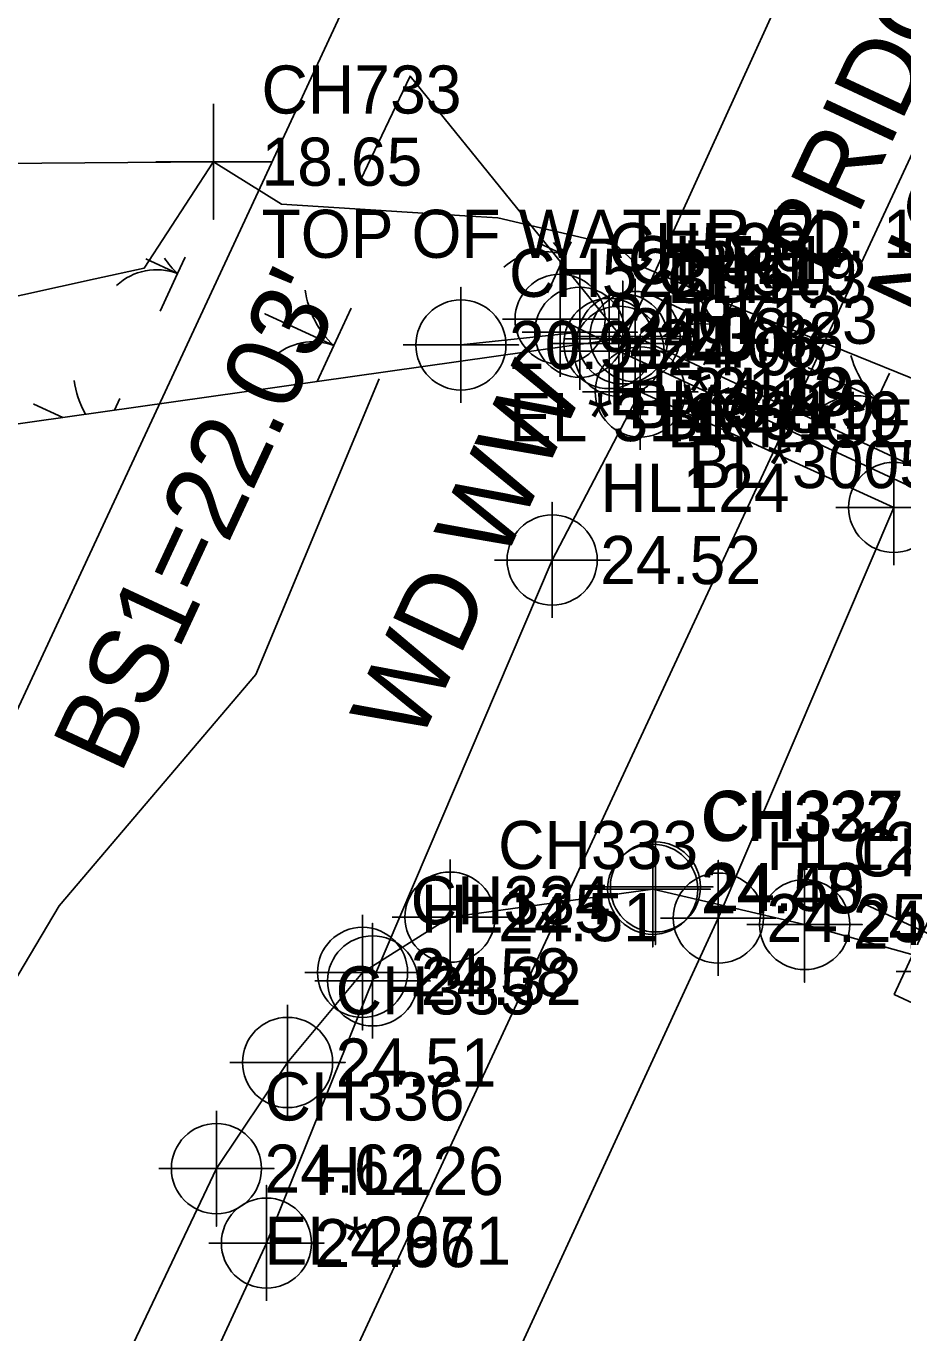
# Model space of a CAD drawing. Extents: x 2532037 to 2533565, y 713396 to 716867.
# Drawn here: x 2532822.3 to 2532867.9, y 715572.7 to 715640.6 of the extents above; entities that cross this region are included whole.
import ezdxf

# ---------------------------------------------------------------- set-up
doc = ezdxf.new("R2010")
doc.units = 0
for name, color, linetype in [('Exist DTM Spot Elevation CELL', 7, 'Continuous'), ('Exist DTM Spot Elevation Cogo Comment', 7, 'Continuous'), ('Exist DTM Spot Elevation Cogo Elevation', 7, 'Continuous'), ('Exist DTM Spot Elevation Cogo Number', 7, 'Continuous'), ('Exist DTM Spot Elevation Leader', 7, 'Continuous'), ('Exist Environmental Wetland Boundary', 7, 'Continuous'), ('Exist Environmental Wetland Boundary Cogo Comment', 7, 'Continuous'), ('Exist Environmental Wetland Boundary Cogo Elevation', 7, 'Continuous'), ('Exist Environmental Wetland Boundary Cogo Number', 7, 'Continuous'), ('Exist Environmental Wetland Boundary Cogo Point CELL', 7, 'Continuous'), ('Exist Horizontal Alignment', 7, 'Continuous'), ('Exist Hydro Jurisdictional Stream or Body of Water', 7, 'Continuous'), ('Exist Hydro Stream or Body of Water', 7, 'Continuous'), ('Exist Right of Way Line', 7, 'Continuous'), ('Exist Roads Soil', 7, 'Continuous'), ('Exist Roads Soil Cogo Comment', 7, 'Continuous'), ('Exist Roads Soil Cogo Elevation', 7, 'Continuous'), ('Exist Roads Soil Cogo Number', 7, 'Continuous'), ('Exist Roads Soil Cogo Point CELL', 7, 'Continuous'), ('Exist Structure Major Bridge Seat Cogo Point CELL', 7, 'Continuous'), ('Exist Structure Major Bridge Seat Leader', 7, 'Continuous'), ('Exist Structure Major Bridge Seat Top Elevation', 7, 'Continuous'), ('Exist Structure Major Bridge WW', 7, 'Continuous'), ('Exist Structure Major Bridge WW Cogo Comment', 7, 'Continuous'), ('Exist Structure Major Bridge WW Cogo Elevation', 7, 'Continuous'), ('Exist Structure Major Bridge WW Cogo Number', 7, 'Continuous'), ('Exist Structure Major Bridge WW Cogo Point CELL', 7, 'Continuous'), ('Exist Structure Major Bridge WW Text', 7, 'Continuous'), ('Exist Structure Major Deck Tunnel Box Culvert', 7, 'Continuous'), ('Exist Structure Major Deck Tunnel Box Culvert Cogo Comment', 7, 'Continuous'), ('Exist Structure Major Deck Tunnel Box Culvert Cogo Elevation', 7, 'Continuous'), ('Exist Structure Major Deck Tunnel Box Culvert Cogo Number', 7, 'Continuous'), ('Exist Structure Major Deck Tunnel Box Culvert Cogo Point CELL', 7, 'Continuous'), ('Exist Structure Major Deck Tunnel Box Culvert Text', 7, 'Continuous'), ('Exist Utilities Power Joint Use Telephone CELL', 7, 'Continuous'), ('Exist Utilities Telephone Pedestal CELL', 7, 'Continuous'), ('Exist Utilities Telephone UG Cable SUE LOS B Cogo Comment', 7, 'Continuous'), ('Exist Utilities Telephone UG Cable SUE LOS B Cogo Elevation', 7, 'Continuous'), ('Exist Utilities Telephone UG Cable SUE LOS B Cogo Number', 7, 'Continuous'), ('Exist Utilities Telephone UG Cable SUE LOS B Cogo Point CELL', 7, 'Continuous'), ('Exist Utilities Telephone UG Cable SUE LOS C', 7, 'Continuous'), ('Scratch_Level_1', 7, 'Continuous')]:
    doc.layers.add(name, color=color, linetype=linetype)

msp = doc.modelspace()

# ---------------------------------------------------------------- linework, layer by layer
at = {"layer": 'Exist DTM Spot Elevation CELL'}
msp.add_lwpolyline([(2532832.011, 715636.536), (2532832.011, 715630.536), (2532832.011, 715633.536), (2532835.011, 715633.536), (2532829.011, 715633.536)], dxfattribs=at)
at = {"layer": 'Exist DTM Spot Elevation Leader'}
msp.add_lwpolyline([(2532832.011, 715633.536), (2532816.373, 715633.398), (2532812.574, 715625.233)], dxfattribs=at)
at = {"layer": 'Exist Environmental Wetland Boundary'}
for p, q in [((2532769.501, 715612.497), (2532853.937, 715624.448)), ((2532853.937, 715624.448), (2532871.679, 715616.187))]:
    msp.add_line(p, q, dxfattribs=at)
at = {"layer": 'Exist Environmental Wetland Boundary Cogo Point CELL'}
msp.add_lwpolyline([(2532853.937, 715627.448), (2532853.937, 715621.448), (2532853.937, 715624.448), (2532856.937, 715624.448), (2532850.937, 715624.448)], dxfattribs=at)
msp.add_circle((2532853.937, 715624.448), 2.344, dxfattribs=at)
at = {"layer": 'Exist Horizontal Alignment'}
msp.add_line((2532720.816, 715316.862), (2532922.836, 715751.084), dxfattribs=at)
at = {"layer": 'Exist Hydro Jurisdictional Stream or Body of Water'}
msp.add_lwpolyline([(2532799.821, 715621.688), (2532825.866, 715627.44), (2532828.419, 715628.003), (2532832.005, 715633.511), (2532832.017, 715633.527), (2532835.552, 715631.335), (2532845.081, 715630.726), (2532846.796, 715630.623), (2532853.018, 715629.166), (2532854.009, 715628.204), (2532858.784, 715626.141), (2532874.956, 715619.591), (2532887.027, 715614.556), (2532890.708, 715612.987), (2532908.235, 715606.211), (2532911.538, 715604.984), (2532924.18, 715599.711), (2532927.478, 715598.382), (2532943.534, 715592.488)], dxfattribs=at)
at = {"layer": 'Exist Hydro Stream or Body of Water'}
msp.add_lwpolyline([(2532840.626, 715622.249), (2532834.214, 715606.883), (2532823.996, 715594.85), (2532817.907, 715584.639), (2532816.632, 715572.085), (2532808.971, 715548.025), (2532795.108, 715512.754), (2532774.804, 715467.828), (2532771.712, 715461.016)], dxfattribs=at)
at = {"layer": 'Exist Right of Way Line'}
msp.add_line((2532693.616, 715329.517), (2532895.636, 715763.738), dxfattribs=at)
at = {"layer": 'Exist Roads Soil'}
for points in [[(2532854.208, 715621.565), (2532849.629, 715612.83), (2532840.293, 715590.952), (2532834.77, 715577.322), (2532814.326, 715533.181), (2532796.183, 715493.991), (2532779.839, 715458.919), (2532764.575, 715425.799), (2532746.469, 715387.058), (2532729.418, 715351.712), (2532714.481, 715319.899), (2532706.788, 715303.318)], [(2532718.476, 715296.339), (2532722.407, 715303.928), (2532737.169, 715334.721), (2532753.884, 715369.29), (2532769.727, 715403.733), (2532784.984, 715435.426), (2532799.766, 715466.715), (2532814.686, 715500.17), (2532830.822, 715535.144), (2532845.407, 715566.333), (2532858.269, 715594.216), (2532867.389, 715615.563), (2532854.208, 715621.565)]]:
    msp.add_lwpolyline(points, dxfattribs=at)
at = {"layer": 'Exist Roads Soil Cogo Point CELL'}
for points in [[(2532854.208, 715618.565), (2532854.208, 715624.565), (2532854.208, 715621.565), (2532857.208, 715621.565), (2532851.208, 715621.565)], [(2532867.389, 715612.563), (2532867.389, 715618.563), (2532867.389, 715615.563), (2532870.389, 715615.563), (2532864.389, 715615.563)], [(2532849.629, 715609.83), (2532849.629, 715615.83), (2532849.629, 715612.83), (2532852.629, 715612.83), (2532846.629, 715612.83)], [(2532858.269, 715591.216), (2532858.269, 715597.216), (2532858.269, 715594.216), (2532861.269, 715594.216), (2532855.269, 715594.216)], [(2532840.293, 715587.952), (2532840.293, 715593.952), (2532840.293, 715590.952), (2532843.293, 715590.952), (2532837.293, 715590.952)], [(2532834.77, 715574.322), (2532834.77, 715580.322), (2532834.77, 715577.322), (2532837.77, 715577.322), (2532831.77, 715577.322)]]:
    msp.add_lwpolyline(points, dxfattribs=at)
for centre in [(2532854.208, 715621.565), (2532867.389, 715615.563), (2532849.629, 715612.83), (2532858.269, 715594.216), (2532840.293, 715590.952), (2532834.77, 715577.322)]:
    msp.add_circle(centre, 2.344, dxfattribs=at)
at = {"layer": 'Exist Structure Major Bridge Seat Cogo Point CELL'}
msp.add_lwpolyline([(2532850.299, 715624.325), (2532856.299, 715624.325), (2532853.299, 715624.325), (2532853.299, 715627.325), (2532853.299, 715621.325)], dxfattribs=at)
msp.add_lwpolyline([(2532850.299, 715624.325), (2532856.299, 715624.325), (2532853.299, 715624.325), (2532853.299, 715627.325), (2532853.299, 715621.325)], dxfattribs=at)
msp.add_circle((2532853.299, 715624.325), 2.344, dxfattribs=at)
msp.add_circle((2532853.299, 715624.325), 2.344, dxfattribs=at)
at = {"layer": 'Exist Structure Major Bridge Seat Leader'}
msp.add_lwpolyline([(2532853.299, 715624.325), (2532842.241, 715637.983), (2532839.656, 715632.568)], dxfattribs=at)
at = {"layer": 'Exist Structure Major Bridge WW'}
for p, q in [((2532852.587, 715624.084), (2532850.044, 715625.345)), ((2532851.064, 715624.669), (2532844.882, 715624.007))]:
    msp.add_line(p, q, dxfattribs=at)
at = {"layer": 'Exist Structure Major Bridge WW Cogo Point CELL'}
for points in [[(2532847.044, 715625.345), (2532853.044, 715625.345), (2532850.044, 715625.345), (2532850.044, 715628.345), (2532850.044, 715622.345)], [(2532848.064, 715624.669), (2532854.064, 715624.669), (2532851.064, 715624.669), (2532851.064, 715627.669), (2532851.064, 715621.669)], [(2532841.882, 715624.007), (2532847.882, 715624.007), (2532844.882, 715624.007), (2532844.882, 715627.007), (2532844.882, 715621.007)], [(2532849.587, 715624.084), (2532855.587, 715624.084), (2532852.587, 715624.084), (2532852.587, 715627.084), (2532852.587, 715621.084)]]:
    msp.add_lwpolyline(points, dxfattribs=at)
for centre in [(2532850.044, 715625.345), (2532851.064, 715624.669), (2532852.587, 715624.084), (2532844.882, 715624.007)]:
    msp.add_circle(centre, 2.344, dxfattribs=at)
at = {"layer": 'Exist Structure Major Deck Tunnel Box Culvert'}
msp.add_lwpolyline([(2532885.805, 715647.494), (2532867.812, 715655.999), (2532853.101, 715623.682), (2532870.979, 715615.38), (2532885.805, 715647.494)], dxfattribs=at)
at = {"layer": 'Exist Structure Major Deck Tunnel Box Culvert Cogo Point CELL'}
msp.add_lwpolyline([(2532850.101, 715623.682), (2532856.101, 715623.682), (2532853.101, 715623.682), (2532853.101, 715626.682), (2532853.101, 715620.682)], dxfattribs=at)
msp.add_lwpolyline([(2532850.101, 715623.682), (2532856.101, 715623.682), (2532853.101, 715623.682), (2532853.101, 715626.682), (2532853.101, 715620.682)], dxfattribs=at)
msp.add_circle((2532853.101, 715623.682), 2.344, dxfattribs=at)
msp.add_circle((2532853.101, 715623.682), 2.344, dxfattribs=at)
at = {"layer": 'Exist Utilities Power Joint Use Telephone CELL'}
msp.add_lwpolyline([(2532868.524, 715587.171), (2532873.34, 715597.435), (2532871.046, 715592.546), (2532865.928, 715594.927)], dxfattribs=at)
at = {"layer": 'Exist Utilities Telephone Pedestal CELL'}
msp.add_lwpolyline([(2532872.492, 715587.893), (2532874.852, 715592.965), (2532869.779, 715595.325), (2532867.419, 715590.253), (2532872.492, 715587.893)], dxfattribs=at)
at = {"layer": 'Exist Utilities Telephone UG Cable SUE LOS B Cogo Point CELL'}
for points in [[(2532854.857, 715598.716), (2532854.857, 715592.716), (2532854.857, 715595.716), (2532857.857, 715595.716), (2532851.857, 715595.716)], [(2532854.999, 715598.838), (2532854.999, 715592.838), (2532854.999, 715595.838), (2532857.999, 715595.838), (2532851.999, 715595.838)], [(2532844.317, 715597.265), (2532844.317, 715591.265), (2532844.317, 715594.265), (2532847.317, 715594.265), (2532841.317, 715594.265)], [(2532862.758, 715596.881), (2532862.758, 715590.881), (2532862.758, 715593.881), (2532865.758, 715593.881), (2532859.758, 715593.881)], [(2532839.766, 715594.394), (2532839.766, 715588.394), (2532839.766, 715591.394), (2532842.766, 715591.394), (2532836.766, 715591.394)], [(2532870.524, 715594.448), (2532870.524, 715588.448), (2532870.524, 715591.448), (2532873.524, 715591.448), (2532867.524, 715591.448)], [(2532835.867, 715589.711), (2532835.867, 715583.711), (2532835.867, 715586.711), (2532838.867, 715586.711), (2532832.867, 715586.711)], [(2532832.169, 715584.195), (2532832.169, 715578.195), (2532832.169, 715581.195), (2532835.169, 715581.195), (2532829.169, 715581.195)]]:
    msp.add_lwpolyline(points, dxfattribs=at)
for centre in [(2532854.857, 715595.716), (2532854.999, 715595.838), (2532844.317, 715594.265), (2532862.758, 715593.881), (2532839.766, 715591.394), (2532835.867, 715586.711), (2532832.169, 715581.195)]:
    msp.add_circle(centre, 2.344, dxfattribs=at)
at = {"layer": 'Exist Utilities Telephone UG Cable SUE LOS C'}
msp.add_lwpolyline([(2532724.197, 715351.236), (2532725.333, 715353.656), (2532742.383, 715388.998), (2532760.472, 715427.703), (2532775.735, 715460.821), (2532792.08, 715495.897), (2532810.221, 715535.082), (2532832.169, 715581.195), (2532835.867, 715586.711), (2532839.766, 715591.394), (2532844.317, 715594.265), (2532854.857, 715595.716), (2532862.758, 715593.881), (2532871.079, 715591.555), (2532871.079, 715591.555)], dxfattribs=at)
at = {"layer": 'Scratch_Level_1'}
msp.add_line((2532826.868, 715620.617), (2532827.151, 715621.231), dxfattribs=at)
for points in [[(2532848.929, 715629.297), (2532850.29, 715628.669), (2532850.611, 715629.364)], [(2532849.388, 715626.716), (2532850.29, 715628.669), (2532848.929, 715629.297)], [(2532828.499, 715628.484), (2532830.148, 715627.723), (2532830.537, 715628.565)], [(2532829.247, 715625.771), (2532830.148, 715627.723), (2532828.499, 715628.484)], [(2532857.51, 715622.967), (2532858.411, 715624.919), (2532854.829, 715626.573), (2532858.411, 715624.919), (2532859.045, 715626.293)], [(2532837.409, 715622.109), (2532838.27, 715623.974), (2532834.688, 715625.627), (2532838.27, 715623.974), (2532839.171, 715625.926)], [(2532865.631, 715619.218), (2532866.533, 715621.17), (2532862.951, 715622.824), (2532866.533, 715621.17), (2532867.167, 715622.544)], [(2532824.177, 715620.236), (2532822.668, 715620.932), (2532824.177, 715620.236)]]:
    msp.add_lwpolyline(points, dxfattribs=at)
for centre, radius, start, end in [((2532853.577, 715632.174), 4.806, 216.3191, 226.84116), ((2532833.436, 715631.229), 4.806, 214.26819, 226.84116), ((2532849.206, 715625.791), 3.075, 69.35932, 132.75394), ((2532829.065, 715624.846), 3.075, 69.35932, 132.75394), ((2532861.698, 715628.425), 4.806, 194.57714, 226.84116), ((2532841.557, 715627.479), 4.806, 187.34643, 226.84116), ((2532857.327, 715622.042), 3.075, 69.35932, 132.75394), ((2532837.186, 715621.097), 3.075, 69.35932, 132.75394), ((2532869.82, 715624.676), 4.806, 194.57714, 226.84116), ((2532829.537, 715622.784), 4.806, 187.34643, 209.69564), ((2532865.449, 715618.293), 3.075, 69.35932, 132.75394)]:
    msp.add_arc(centre, radius, start, end, dxfattribs=at)

# ---------------------------------------------------------------- texts
at = {"layer": 'Exist DTM Spot Elevation Cogo Comment'}
msp.add_text("TOP OF WATER EL: 18.65' @ 11:22 AM, 12-6-18", height=2.5, dxfattribs=at).set_placement((2532834.511, 715628.536))
at = {"layer": 'Exist DTM Spot Elevation Cogo Elevation'}
msp.add_text('18.65', height=2.5, dxfattribs=at).set_placement((2532834.511, 715632.286))
at = {"layer": 'Exist DTM Spot Elevation Cogo Number'}
msp.add_text('CH733', height=2.5, dxfattribs=at).set_placement((2532834.511, 715636.036))
at = {"layer": 'Exist Environmental Wetland Boundary Cogo Comment'}
msp.add_text('WB8', height=2.5, dxfattribs=at).set_placement((2532856.437, 715619.448))
at = {"layer": 'Exist Environmental Wetland Boundary Cogo Elevation'}
msp.add_text('23.88', height=2.5, dxfattribs=at).set_placement((2532856.437, 715623.198))
at = {"layer": 'Exist Environmental Wetland Boundary Cogo Number'}
msp.add_text('RR1', height=2.5, dxfattribs=at).set_placement((2532856.437, 715626.948))
at = {"layer": 'Exist Roads Soil Cogo Comment'}
msp.add_text('BL*3005', height=2.5, dxfattribs=at).set_placement((2532856.708, 715616.565))
at = {"layer": 'Exist Roads Soil Cogo Elevation'}
for s, p in [('24.13', (2532856.708, 715620.315)), ('24.52', (2532852.129, 715611.58)), ('24.25', (2532860.769, 715592.966)), ('24.32', (2532842.793, 715589.702)), ('24.66', (2532837.27, 715576.072))]:
    msp.add_text(s, height=2.5, dxfattribs=at).set_placement(p)
at = {"layer": 'Exist Roads Soil Cogo Number'}
for s, p in [('HL123', (2532856.708, 715624.065)), ('HL124', (2532852.129, 715615.33)), ('HL121', (2532860.769, 715596.716)), ('HL125', (2532842.793, 715593.452)), ('HL126', (2532837.27, 715579.822))]:
    msp.add_text(s, height=2.5, dxfattribs=at).set_placement(p)
at = {"layer": 'Exist Structure Major Bridge Seat Top Elevation'}
for s, p in [("BS1=22.03'", (2532827.172, 715601.614)), ("BS2=21.99'", (2532870.557, 715548.591))]:
    msp.add_text(s, height=4, rotation=65.05, dxfattribs=at).set_placement(p)
at = {"layer": 'Exist Structure Major Bridge WW Cogo Comment'}
for s, p in [('EL*3119', (2532852.544, 715620.345)), ('BL*3119', (2532853.564, 715619.669)), ('EL*3119', (2532847.382, 715619.007)), ('BL*3119', (2532855.087, 715619.084))]:
    msp.add_text(s, height=2.5, dxfattribs=at).set_placement(p)
at = {"layer": 'Exist Structure Major Bridge WW Cogo Elevation'}
for s, p in [('24.07', (2532852.544, 715624.095)), ('24.08', (2532853.564, 715623.419)), ('20.91', (2532847.382, 715622.757)), ('24.06', (2532855.087, 715622.834))]:
    msp.add_text(s, height=2.5, dxfattribs=at).set_placement(p)
at = {"layer": 'Exist Structure Major Bridge WW Cogo Number'}
for s, p in [('CH520', (2532852.544, 715627.845)), ('CH521', (2532853.564, 715627.169)), ('CH522', (2532847.382, 715626.507)), ('CH519', (2532855.087, 715626.584))]:
    msp.add_text(s, height=2.5, dxfattribs=at).set_placement(p)
at = {"layer": 'Exist Structure Major Bridge WW Text'}
msp.add_text('WD WW', height=4, rotation=65.05, dxfattribs=at).set_placement((2532842.677, 715603.156))
at = {"layer": 'Exist Structure Major Deck Tunnel Box Culvert Cogo Comment'}
msp.add_text('BRIDGE DECK 1', height=2.5, dxfattribs=at).set_placement((2532855.601, 715618.682))
at = {"layer": 'Exist Structure Major Deck Tunnel Box Culvert Cogo Elevation'}
msp.add_text('24.06', height=2.5, dxfattribs=at).set_placement((2532855.601, 715622.432))
msp.add_text('24.06', height=2.5, dxfattribs=at).set_placement((2532855.601, 715622.432))
at = {"layer": 'Exist Structure Major Deck Tunnel Box Culvert Cogo Number'}
for s in ['CH503', 'BD1']:
    msp.add_text(s, height=2.5, dxfattribs=at).set_placement((2532855.601, 715626.182))
at = {"layer": 'Exist Structure Major Deck Tunnel Box Culvert Text'}
for s, p in [('BRIDGE', (2532864, 715627.432)), ('NO. 123', (2532869.46, 715624.944))]:
    msp.add_text(s, height=4, rotation=65.05, dxfattribs=at).set_placement(p)
at = {"layer": 'Exist Utilities Telephone UG Cable SUE LOS B Cogo Comment'}
msp.add_text('EL*2971', height=2.5, dxfattribs=at).set_placement((2532834.669, 715576.195))
at = {"layer": 'Exist Utilities Telephone UG Cable SUE LOS B Cogo Elevation'}
for s, p in [('24.48', (2532857.357, 715594.466)), ('24.50', (2532857.499, 715594.588)), ('24.51', (2532846.817, 715593.015)), ('24.16', (2532865.258, 715592.631)), ('24.58', (2532842.266, 715590.144)), ('24.51', (2532838.367, 715585.461)), ('24.62', (2532834.669, 715579.945))]:
    msp.add_text(s, height=2.5, dxfattribs=at).set_placement(p)
at = {"layer": 'Exist Utilities Telephone UG Cable SUE LOS B Cogo Number'}
for s, p in [('CH332', (2532857.357, 715598.216)), ('CH327', (2532857.499, 715598.338)), ('CH333', (2532846.817, 715596.765)), ('CH326', (2532865.258, 715596.381)), ('CH334', (2532842.266, 715593.894)), ('CH335', (2532838.367, 715589.211)), ('CH336', (2532834.669, 715583.695))]:
    msp.add_text(s, height=2.5, dxfattribs=at).set_placement(p)

doc.saveas('drawing.dxf')
